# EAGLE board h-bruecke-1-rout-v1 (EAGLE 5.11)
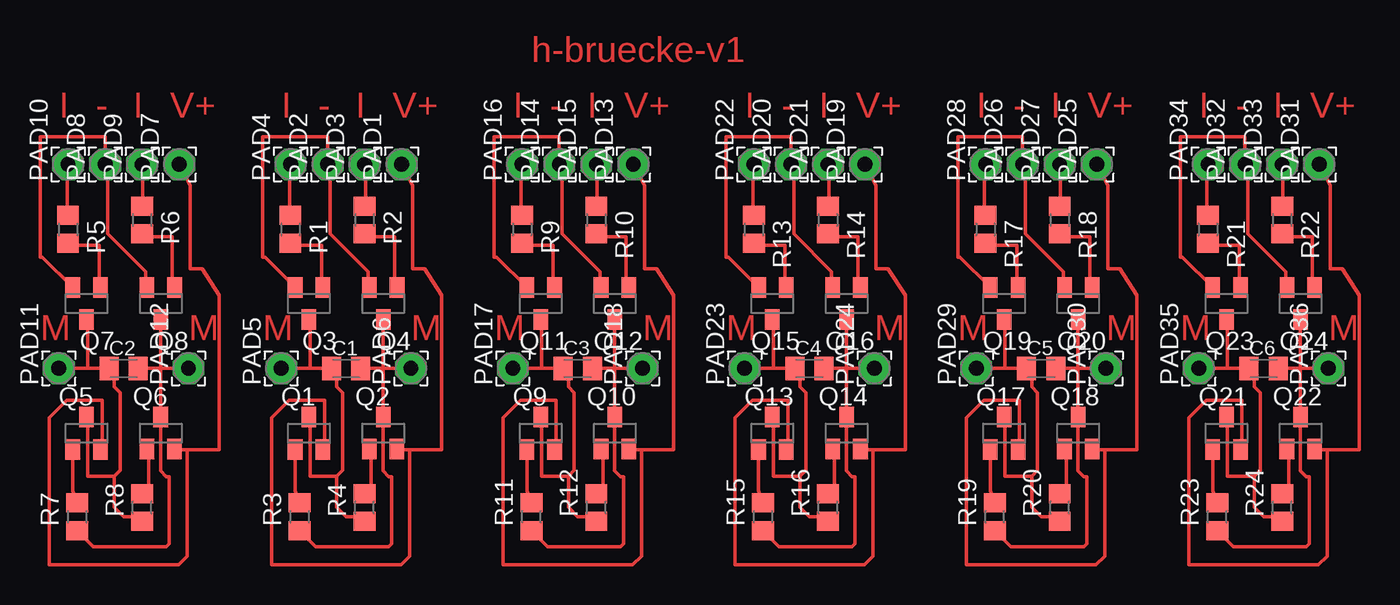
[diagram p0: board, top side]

No outline drawn. Coordinates in mm, seen from the top.
Copper layers (1*16): Top 0.035mm / dielectric 1.5mm / Bottom 0.035mm
Design rules "Bilex-DRU": minimum track width 10mil, minimum drill 24mil, track to track 10mil, track to pad 10mil, pad to pad 10mil, via to via 10mil, smd to smd 10mil, copper to edge 40mil, drill to drill 8mil, minimum pad ring 10mil, minimum via ring 8mil, stop-mask expansion 4mil, vias tented up to drill 0mil, thermal gap 10mil
Net classes: 0 default: width 0.254 mm, clearance 0.254 mm

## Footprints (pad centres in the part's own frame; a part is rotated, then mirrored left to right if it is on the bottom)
C0805K = smd 1.3 x 1.6: 1 -1,0; 2 1,0
2,15/1,0 = drill 1.016 pad 2.159 octagon: 1 0,0
SOT23-BEC = smd 1 x 1.4: B -0.95,-1.1; C 0,1.1; E 0.95,-1.1
R0805 = smd 1.3 x 1.5: 1 -0.95,0; 2 0.95,0

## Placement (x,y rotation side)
C1  100nf  [C0805K]  22.23,13.97 0 top
C2  100nf  [C0805K]  6.99,13.97 0 top
C3  100nf  [C0805K]  38.1,13.97 0 top
C4  100nf  [C0805K]  53.98,13.97 0 top
C5  100nf  [C0805K]  69.85,13.97 0 top
C6  100nf  [C0805K]  85.09,13.97 0 top
PAD1  [2,15/1,0]  26.03,27.95 90 top
PAD2  [2,15/1,0]  20.96,27.95 90 top
PAD3  [2,15/1,0]  23.5,27.94 90 top
PAD4  [2,15/1,0]  18.42,27.94 90 top
PAD5  [2,15/1,0]  17.78,13.97 90 top
PAD6  [2,15/1,0]  26.67,13.97 90 top
PAD7  [2,15/1,0]  10.79,27.95 90 top
PAD8  [2,15/1,0]  5.72,27.95 90 top
PAD9  [2,15/1,0]  8.26,27.94 90 top
PAD10  [2,15/1,0]  3.18,27.94 90 top
PAD11  [2,15/1,0]  2.54,13.97 90 top
PAD12  [2,15/1,0]  11.43,13.97 90 top
PAD13  [2,15/1,0]  41.91,27.95 90 top
PAD14  [2,15/1,0]  36.84,27.95 90 top
PAD15  [2,15/1,0]  39.37,27.94 90 top
PAD16  [2,15/1,0]  34.29,27.94 90 top
PAD17  [2,15/1,0]  33.66,13.97 90 top
PAD18  [2,15/1,0]  42.55,13.97 90 top
PAD19  [2,15/1,0]  57.78,27.95 90 top
PAD20  [2,15/1,0]  52.72,27.95 90 top
PAD21  [2,15/1,0]  55.25,27.94 90 top
PAD22  [2,15/1,0]  50.17,27.94 90 top
PAD23  [2,15/1,0]  49.53,13.97 90 top
PAD24  [2,15/1,0]  58.42,13.97 90 top
PAD25  [2,15/1,0]  73.66,27.95 90 top
PAD26  [2,15/1,0]  68.59,27.95 90 top
PAD27  [2,15/1,0]  71.12,27.94 90 top
PAD28  [2,15/1,0]  66.04,27.94 90 top
PAD29  [2,15/1,0]  65.41,13.97 90 top
PAD30  [2,15/1,0]  74.3,13.97 90 top
PAD31  [2,15/1,0]  88.9,27.95 90 top
PAD32  [2,15/1,0]  83.83,27.95 90 top
PAD33  [2,15/1,0]  86.36,27.94 90 top
PAD34  [2,15/1,0]  81.28,27.94 90 top
PAD35  [2,15/1,0]  80.64,13.97 90 top
PAD36  [2,15/1,0]  89.53,13.97 90 top
Q1  BC 807  [SOT23-BEC]  19.69,9.53 0 top
Q2  BC 807  [SOT23-BEC]  24.77,9.54 0 top
Q3  BC 817  [SOT23-BEC]  19.69,18.42 180 top
Q4  BC 817  [SOT23-BEC]  24.77,18.41 180 top
Q5  BC 807  [SOT23-BEC]  4.45,9.53 0 top
Q6  BC 807  [SOT23-BEC]  9.53,9.54 0 top
Q7  BC 817  [SOT23-BEC]  4.45,18.42 180 top
Q8  BC 817  [SOT23-BEC]  9.53,18.41 180 top
Q9  BC 807  [SOT23-BEC]  35.56,9.53 0 top
Q10  BC 807  [SOT23-BEC]  40.64,9.54 0 top
Q11  BC 817  [SOT23-BEC]  35.56,18.42 180 top
Q12  BC 817  [SOT23-BEC]  40.65,18.41 180 top
Q13  BC 807  [SOT23-BEC]  51.44,9.53 0 top
Q14  BC 807  [SOT23-BEC]  56.52,9.54 0 top
Q15  BC 817  [SOT23-BEC]  51.44,18.42 180 top
Q16  BC 817  [SOT23-BEC]  56.52,18.41 180 top
Q17  BC 807  [SOT23-BEC]  67.31,9.53 0 top
Q18  BC 807  [SOT23-BEC]  72.39,9.54 0 top
Q19  BC 817  [SOT23-BEC]  67.31,18.42 180 top
Q20  BC 817  [SOT23-BEC]  72.4,18.41 180 top
Q21  BC 807  [SOT23-BEC]  82.55,9.53 0 top
Q22  BC 807  [SOT23-BEC]  87.63,9.54 0 top
Q23  BC 817  [SOT23-BEC]  82.55,18.42 180 top
Q24  BC 817  [SOT23-BEC]  87.64,18.41 180 top
R1  1K  [R0805]  18.41,23.5 270 top
R2  1K  [R0805]  23.5,24.13 270 top
R3  1K  [R0805]  19.05,3.81 90 top
R4  1K  [R0805]  23.5,4.45 90 top
R5  1K  [R0805]  3.17,23.5 270 top
R6  1K  [R0805]  8.26,24.13 270 top
R7  1K  [R0805]  3.81,3.81 90 top
R8  1K  [R0805]  8.26,4.45 90 top
R9  1K  [R0805]  34.29,23.5 270 top
R10  1K  [R0805]  39.37,24.13 270 top
R11  1K  [R0805]  34.92,3.81 90 top
R12  1K  [R0805]  39.37,4.45 90 top
R13  1K  [R0805]  50.16,23.5 270 top
R14  1K  [R0805]  55.24,24.13 270 top
R15  1K  [R0805]  50.8,3.81 90 top
R16  1K  [R0805]  55.24,4.45 90 top
R17  1K  [R0805]  66.04,23.5 270 top
R18  1K  [R0805]  71.12,24.13 270 top
R19  1K  [R0805]  66.67,3.81 90 top
R20  1K  [R0805]  71.12,4.45 90 top
R21  1K  [R0805]  81.28,23.5 270 top
R22  1K  [R0805]  86.36,24.13 270 top
R23  1K  [R0805]  81.92,3.81 90 top
R24  1K  [R0805]  86.36,4.45 90 top

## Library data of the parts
C1-C6 R1-R24 = rcl
PAD1-PAD36 = wirepad
Q1 Q2 Q5 Q6 Q9 Q10 Q13 Q14 Q17 Q18 Q21 Q22 = transistor-npn
Q3 Q4 Q7 Q8 Q11 Q12 Q15 Q16 Q19 Q20 Q23 Q24 = transistor-pnp

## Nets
GND: PAD2.1 Q3.E Q4.E
GND1: PAD8.1 Q7.E Q8.E
GND2: PAD14.1 Q11.E Q12.E
GND3: PAD20.1 Q15.E Q16.E
GND4: PAD26.1 Q19.E Q20.E
GND5: PAD32.1 Q23.E Q24.E
N$1: Q3.B R1.2
N$2: Q4.B R2.2
N$3: C1.1 PAD5.1 Q1.C Q3.C R4.1
N$4: C1.2 PAD6.1 Q2.C Q4.C R3.1
N$5: Q2.B R4.2
N$6: Q1.B R3.2
N$7: C2.1 PAD11.1 Q5.C Q7.C R8.1
N$8: PAD4.1 R1.1
N$9: PAD3.1 R2.1
N$10: C2.2 PAD12.1 Q6.C Q8.C R7.1
N$11: Q5.B R7.2
N$12: PAD10.1 R5.1
N$13: Q7.B R5.2
N$14: Q8.B R6.2
N$15: Q6.B R8.2
N$16: PAD9.1 R6.1
N$17: C3.1 PAD17.1 Q9.C Q11.C R12.1
N$18: C3.2 PAD18.1 Q10.C Q12.C R11.1
N$19: Q9.B R11.2
N$20: PAD16.1 R9.1
N$21: Q11.B R9.2
N$22: Q12.B R10.2
N$23: Q10.B R12.2
N$24: PAD15.1 R10.1
N$25: C4.1 PAD23.1 Q13.C Q15.C R16.1
N$26: C4.2 PAD24.1 Q14.C Q16.C R15.1
N$27: Q13.B R15.2
N$28: PAD22.1 R13.1
N$29: Q15.B R13.2
N$30: Q16.B R14.2
N$31: Q14.B R16.2
N$32: PAD21.1 R14.1
N$33: C5.1 PAD29.1 Q17.C Q19.C R20.1
N$34: C5.2 PAD30.1 Q18.C Q20.C R19.1
N$35: Q17.B R19.2
N$36: PAD28.1 R17.1
N$37: Q19.B R17.2
N$38: Q20.B R18.2
N$39: Q18.B R20.2
N$40: PAD27.1 R18.1
N$41: C6.1 PAD35.1 Q21.C Q23.C R24.1
N$42: C6.2 PAD36.1 Q22.C Q24.C R23.1
N$43: Q21.B R23.2
N$44: PAD34.1 R21.1
N$45: Q23.B R21.2
N$46: Q24.B R22.2
N$47: Q22.B R24.2
N$48: PAD33.1 R22.1
V+: PAD1.1 Q1.E Q2.E
V+1: PAD7.1 Q5.E Q6.E
V+2: PAD13.1 Q9.E Q10.E
V+3: PAD19.1 Q13.E Q14.E
V+4: PAD25.1 Q17.E Q18.E
V+5: PAD31.1 Q21.E Q22.E

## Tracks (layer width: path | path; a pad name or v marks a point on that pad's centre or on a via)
GND
  Top 0.254: Q4.E 23.75,19.59 23.75,20.59 21.15,23.19 21.15,27.79 PAD2.1 20.95,27.99 20.95,29.84 16.51,29.84 16.51,21.59 16.67,21.59 Q3.E 18.55,19.59
GND1
  Top 0.254: Q8.E 8.51,19.59 8.51,20.59 5.91,23.19 5.91,27.79 PAD8.1 5.71,27.99 5.71,29.84 1.27,29.84 1.27,21.59 1.43,21.59 Q7.E 3.31,19.59
GND2
  Top 0.254: Q12.E 39.62,19.59 39.62,20.59 37.02,23.19 37.02,27.79 PAD14.1 36.83,27.99 36.83,29.84 32.38,29.84 32.38,21.59 32.54,21.59 Q11.E 34.42,19.59
GND3
  Top 0.254: Q16.E 55.5,19.59 55.5,20.59 52.9,23.19 52.9,27.79 PAD20.1 52.7,27.99 52.7,29.84 48.26,29.84 48.26,21.59 48.42,21.59 Q15.E 50.3,19.59
GND4
  Top 0.254: Q20.E 71.38,19.59 71.38,20.59 68.78,23.19 68.78,27.79 PAD26.1 68.58,27.99 68.58,29.84 64.14,29.84 64.14,21.59 64.29,21.59 Q19.E 66.17,19.59
GND5
  Top 0.254: Q24.E 86.61,19.59 86.61,20.59 84.02,23.19 84.02,27.79 PAD32.1 83.81,27.99 83.81,29.84 79.38,29.84 79.38,21.59 79.53,21.59 Q23.E 81.42,19.59
N$1
  Top 0.254: Q3.B 20.55,19.59 20.55,22.39 18.55,22.39 R1.2
N$2
  Top 0.254: Q4.B 25.55,19.59 25.55,22.99 23.55,22.99 R2.2
N$3
  Top 0.254: 19.75,13.99 19.75,17.19 Q3.C | 19.75,13.99 21.15,13.99 C1.1 21.59,13.61 21.59,12.7 21.98,12.3 21.98,6.99 21.59,6.59 | 19.75,13.99 17.95,13.99 PAD5.1 | 21.59,6.59 19.75,6.59 19.75,10.59 Q1.C | 23.95,3.59 R4.1 23.82,3.81 22.23,3.81 21.59,4.45 21.59,6.59
N$4
  Top 0.254: 24.75,13.99 24.75,17.19 Q4.C | 24.75,13.99 23.35,13.99 C1.2 | 24.75,13.99 24.75,10.79 Q2.C 24.75,10.59 24.75,6.96 25.15,6.55 25.35,6.55 25.35,1.96 25.15,1.75 20.15,1.75 19.15,2.75 R3.1 | 24.75,13.99 26.55,13.99 PAD6.1
N$5
  Top 0.254: Q2.B 23.95,8.39 23.95,5.59 R4.2
N$6
  Top 0.254: Q1.B 18.75,8.39 18.75,5.59 18.95,4.96 R3.2
N$7
  Top 0.254: 4.51,13.99 4.51,17.19 Q7.C | 4.51,13.99 5.91,13.99 C2.1 6.35,13.61 6.35,12.7 6.75,12.3 6.75,6.99 6.34,6.59 | 4.51,13.99 2.71,13.99 PAD11.1 | 6.34,6.59 4.51,6.59 4.51,10.59 Q5.C | 8.71,3.59 R8.1 8.57,3.81 6.99,3.81 6.34,4.45 6.34,6.59
N$8
  Top 0.254: R1.1 18.35,24.59 18.35,27.79 PAD4.1
N$9
  Top 0.254: R2.1 23.55,25.19 23.55,27.79 PAD3.1
N$10
  Top 0.254: 9.51,13.99 9.51,17.19 Q8.C | 9.51,13.99 8.11,13.99 C2.2 | 9.51,13.99 9.51,10.79 Q6.C 9.51,10.59 9.51,6.96 9.91,6.55 10.11,6.55 10.11,1.96 9.91,1.75 4.91,1.75 3.91,2.75 R7.1 | 9.51,13.99 11.31,13.99 PAD12.1
N$11
  Top 0.254: Q5.B 3.51,8.39 3.51,5.59 3.71,4.96 R7.2
N$12
  Top 0.254: R5.1 3.11,24.59 3.11,27.79 PAD10.1
N$13
  Top 0.254: Q7.B 5.31,19.59 5.31,22.39 3.31,22.39 R5.2
N$14
  Top 0.254: Q8.B 10.31,19.59 10.31,22.99 8.31,22.99 R6.2
N$15
  Top 0.254: Q6.B 8.71,8.39 8.71,5.59 R8.2
N$16
  Top 0.254: R6.1 8.31,25.19 8.31,27.79 PAD9.1
N$17
  Top 0.254: 35.62,13.99 35.62,17.19 Q11.C | 35.62,13.99 37.02,13.99 C3.1 37.47,13.61 37.47,12.7 37.86,12.3 37.86,6.99 37.46,6.59 | 35.62,13.99 33.83,13.99 PAD17.1 | 37.46,6.59 35.62,6.59 35.62,10.59 Q9.C | 39.83,3.59 R12.1 39.69,3.81 38.1,3.81 37.46,4.45 37.46,6.59
N$18
  Top 0.254: 40.62,13.99 40.62,17.19 Q12.C | 40.62,13.99 39.23,13.99 C3.2 | 40.62,13.99 40.62,10.79 Q10.C 40.62,10.59 40.62,6.96 41.02,6.55 41.23,6.55 41.23,1.96 41.02,1.75 36.02,1.75 35.02,2.75 R11.1 | 40.62,13.99 42.42,13.99 PAD18.1
N$19
  Top 0.254: Q9.B 34.62,8.39 34.62,5.59 34.83,4.96 R11.2
N$20
  Top 0.254: R9.1 34.23,24.59 34.23,27.79 PAD16.1
N$21
  Top 0.254: Q11.B 36.42,19.59 36.42,22.39 34.42,22.39 R9.2
N$22
  Top 0.254: Q12.B 41.42,19.59 41.42,22.99 39.42,22.99 R10.2
N$23
  Top 0.254: Q10.B 39.83,8.39 39.83,5.59 R12.2
N$24
  Top 0.254: R10.1 39.42,25.19 39.42,27.79 PAD15.1
N$25
  Top 0.254: 51.5,13.99 51.5,17.19 Q15.C | 51.5,13.99 52.9,13.99 C4.1 53.34,13.61 53.34,12.7 53.73,12.3 53.73,6.99 53.34,6.59 | 51.5,13.99 49.7,13.99 PAD23.1 | 53.34,6.59 51.5,6.59 51.5,10.59 Q13.C | 55.7,3.59 R16.1 55.56,3.81 53.98,3.81 53.34,4.45 53.34,6.59
N$26
  Top 0.254: 56.5,13.99 56.5,17.19 Q16.C | 56.5,13.99 55.1,13.99 C4.2 | 56.5,13.99 56.5,10.79 Q14.C 56.5,10.59 56.5,6.96 56.9,6.55 57.1,6.55 57.1,1.96 56.9,1.75 51.9,1.75 50.9,2.75 R15.1 | 56.5,13.99 58.3,13.99 PAD24.1
N$27
  Top 0.254: Q13.B 50.5,8.39 50.5,5.59 50.7,4.96 R15.2
N$28
  Top 0.254: R13.1 50.1,24.59 50.1,27.79 PAD22.1
N$29
  Top 0.254: Q15.B 52.3,19.59 52.3,22.39 50.3,22.39 R13.2
N$30
  Top 0.254: Q16.B 57.3,19.59 57.3,22.99 55.3,22.99 R14.2
N$31
  Top 0.254: Q14.B 55.7,8.39 55.7,5.59 R16.2
N$32
  Top 0.254: R14.1 55.3,25.19 55.3,27.79 PAD21.1
N$33
  Top 0.254: 67.38,13.99 67.38,17.19 Q19.C | 67.38,13.99 68.78,13.99 C5.1 69.22,13.61 69.22,12.7 69.61,12.3 69.61,6.99 69.21,6.59 | 67.38,13.99 65.58,13.99 PAD29.1 | 69.21,6.59 67.38,6.59 67.38,10.59 Q17.C | 71.58,3.59 R20.1 71.44,3.81 69.85,3.81 69.21,4.45 69.21,6.59
N$34
  Top 0.254: 72.38,13.99 72.38,17.19 Q20.C | 72.38,13.99 70.97,13.99 C5.2 | 72.38,13.99 72.38,10.79 Q18.C 72.38,10.59 72.38,6.96 72.78,6.55 72.97,6.55 72.97,1.96 72.78,1.75 67.78,1.75 66.78,2.75 R19.1 | 72.38,13.99 74.17,13.99 PAD30.1
N$35
  Top 0.254: Q17.B 66.38,8.39 66.38,5.59 66.58,4.96 R19.2
N$36
  Top 0.254: R17.1 65.97,24.59 65.97,27.79 PAD28.1
N$37
  Top 0.254: Q19.B 68.17,19.59 68.17,22.39 66.17,22.39 R17.2
N$38
  Top 0.254: Q20.B 73.17,19.59 73.17,22.99 71.17,22.99 R18.2
N$39
  Top 0.254: Q18.B 71.58,8.39 71.58,5.59 R20.2
N$40
  Top 0.254: R18.1 71.17,25.19 71.17,27.79 PAD27.1
N$41
  Top 0.254: 82.61,13.99 82.61,17.19 Q23.C | 82.61,13.99 84.02,13.99 C6.1 84.45,13.61 84.45,12.7 84.85,12.3 84.85,6.99 84.45,6.59 | 82.61,13.99 80.81,13.99 PAD35.1 | 84.45,6.59 82.61,6.59 82.61,10.59 Q21.C | 86.81,3.59 R24.1 86.68,3.81 85.09,3.81 84.45,4.45 84.45,6.59
N$42
  Top 0.254: 87.61,13.99 87.61,17.19 Q24.C | 87.61,13.99 86.22,13.99 C6.2 | 87.61,13.99 87.61,10.79 Q22.C 87.61,10.59 87.61,6.96 88.02,6.55 88.22,6.55 88.22,1.96 88.02,1.75 83.02,1.75 82.02,2.75 R23.1 | 87.61,13.99 89.42,13.99 PAD36.1
N$43
  Top 0.254: Q21.B 81.61,8.39 81.61,5.59 81.81,4.96 R23.2
N$44
  Top 0.254: R21.1 81.22,24.59 81.22,27.79 PAD34.1
N$45
  Top 0.254: Q23.B 83.42,19.59 83.42,22.39 81.42,22.39 R21.2
N$46
  Top 0.254: Q24.B 88.42,19.59 88.42,22.99 86.42,22.99 R22.2
N$47
  Top 0.254: Q22.B 86.81,8.39 86.81,5.59 R24.2
N$48
  Top 0.254: R22.1 86.42,25.19 86.42,27.79 PAD33.1
V+
  Top 0.254: 26.59,8.39 26.59,1.12 25.98,0.52 17.11,0.52 17.11,10.59 18.32,11.79 20.75,11.79 20.75,8.59 Q1.E | 26.59,8.39 25.75,8.39 Q2.E 26.59,8.39 | 26.59,8.39 28.79,8.39 28.79,18.99 27.62,20.79 26.79,20.79 26.79,26.52 PAD1.1
V+1
  Top 0.254: 11.35,8.39 11.35,1.12 10.74,0.52 1.88,0.52 1.88,10.59 3.08,11.79 5.51,11.79 5.51,8.59 Q5.E | 11.35,8.39 10.51,8.39 Q6.E 11.35,8.39 | 11.35,8.39 13.54,8.39 13.54,18.99 12.38,20.79 11.54,20.79 11.54,26.52 PAD7.1
V+2
  Top 0.254: 42.46,8.39 42.46,1.12 41.86,0.52 32.99,0.52 32.99,10.59 34.19,11.79 36.62,11.79 36.62,8.59 Q9.E | 42.46,8.39 41.62,8.39 Q10.E 42.46,8.39 | 42.46,8.39 44.66,8.39 44.66,18.99 43.49,20.79 42.66,20.79 42.66,26.52 PAD13.1
V+3
  Top 0.254: 58.34,8.39 58.34,1.12 57.73,0.52 48.87,0.52 48.87,10.59 50.06,11.79 52.5,11.79 52.5,8.59 Q13.E | 58.34,8.39 57.5,8.39 Q14.E 58.34,8.39 | 58.34,8.39 60.53,8.39 60.53,18.99 59.37,20.79 58.53,20.79 58.53,26.52 PAD19.1
V+4
  Top 0.254: 74.21,8.39 74.21,1.12 73.61,0.52 64.74,0.52 64.74,10.59 65.94,11.79 68.38,11.79 68.38,8.59 Q17.E | 74.21,8.39 73.38,8.39 Q18.E 74.21,8.39 | 74.21,8.39 76.41,8.39 76.41,18.99 75.25,20.79 74.41,20.79 74.41,26.52 PAD25.1
V+5
  Top 0.254: 89.45,8.39 89.45,1.12 88.85,0.52 79.98,0.52 79.98,10.59 81.18,11.79 83.61,11.79 83.61,8.59 Q21.E | 89.45,8.39 88.61,8.39 Q22.E 89.45,8.39 | 89.45,8.39 91.65,8.39 91.65,18.99 90.48,20.79 89.65,20.79 89.65,26.52 PAD31.1

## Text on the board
Top: h-bruecke-v1 | I | - | I | V+ | I | - | I | V+ | I | - | I | V+ | I | - | I | V+ | I | - | I | V+ | I | - | I | V+ | M | M | M | M | M | M | M | M | M | M | M | M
